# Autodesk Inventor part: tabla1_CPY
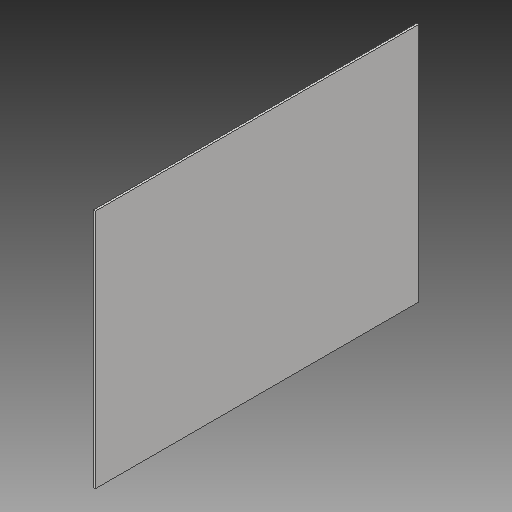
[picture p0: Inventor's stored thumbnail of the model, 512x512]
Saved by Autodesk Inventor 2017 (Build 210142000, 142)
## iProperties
Created: 2017-11
Part Number: tabla1_CPY
Material: Generic
Document SubType Name: Modeling
Designer: iusti
Density: 1 g/cm^3
Appearance: Default
Author: iusti
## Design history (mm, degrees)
sketch "Sketch1"
  geometry: L1 (599.54, 773.5)-(-550.46, 773.5); L2 (-550.46, 773.5)-(-550.46, -773.5); L3 (-550.46, -773.5)-(599.54, -773.5); L4 (599.54, -773.5)-(599.54, 773.5); L5 (599.54, 773.5)-(-550.46, -773.5); L6 (-550.46, 773.5)-(599.54, -773.5); 2 further points
  constraints: 12 end point, 2 midpoint, 2 parallel, 1 horizontal, 1 perpendicular
  dimensions: "d0" = 1547 distance of L3.end L1.start; "d2" = 1150 distance of L1.start L1.end
extrude "Extrusion1" new body sketch "Sketch1" distance "d3" = 10; taper "d4" = 0 deg
body "Solid1"
